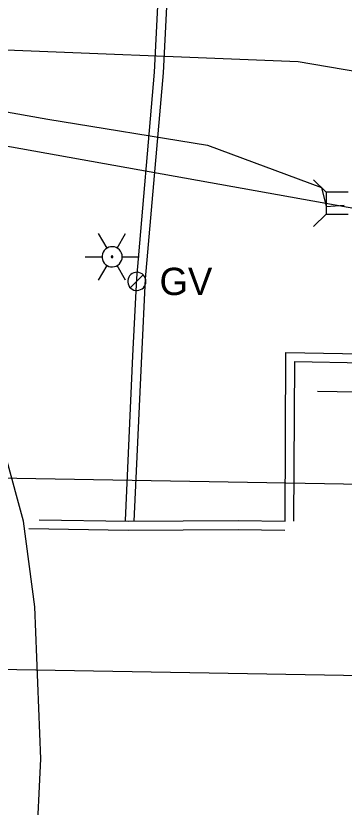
# Model space of a CAD drawing. Extents: x 596028 to 606371, y 330010 to 403088.
# Drawn here: x 604589.6 to 604635.9, y 337984.6 to 338096.2 of the extents above; entities that cross this region are included whole.
import ezdxf

# ---------------------------------------------------------------- set-up
doc = ezdxf.new("R2010")
doc.units = 0
for name, color, linetype in [('E_FTMS_Conduit', 7, 'Continuous'), ('E_LTG', 7, 'Continuous'), ('E_UTL_G', 7, 'Continuous'), ('E_UTL_G_UG', 7, 'Continuous'), ('E_UTL_Overhead', 7, 'Continuous'), ('E_UTL_SAN_UG_MMSD', 7, 'Continuous'), ('E_UTL_T', 7, 'Continuous'), ('E_UTL_T_UG', 7, 'Continuous')]:
    doc.layers.add(name, color=color, linetype=linetype)

# ---------------------------------------------------------------- blocks, each defined once
blk = doc.blocks.new('ACAD_PROXY_ENTITY_15')
at = {"layer": 'E_LTG'}
for points in [[(1843663.8, 1030159.59), (1843660.17, 1030165.87)], [(1843668.16, 1030159.59), (1843671.79, 1030165.87)], [(1843670.34, 1030155.82), (1843670.26, 1030156.64), (1843670.02, 1030157.44), (1843669.64, 1030158.17), (1843669.13, 1030158.82), (1843668.51, 1030159.36), (1843667.79, 1030159.78), (1843667.01, 1030160.05), (1843666.19, 1030160.17), (1843665.36, 1030160.13), (1843664.56, 1030159.93), (1843663.8, 1030159.59), (1843663.13, 1030159.11), (1843662.56, 1030158.51), (1843662.11, 1030157.81), (1843661.8, 1030157.04), (1843661.64, 1030156.23), (1843661.64, 1030155.4), (1843661.8, 1030154.59), (1843662.11, 1030153.82), (1843662.56, 1030153.12), (1843663.13, 1030152.52), (1843663.8, 1030152.04), (1843664.56, 1030151.7), (1843665.36, 1030151.51), (1843666.19, 1030151.47), (1843667.01, 1030151.58), (1843667.79, 1030151.85), (1843668.51, 1030152.27), (1843669.13, 1030152.81), (1843669.64, 1030153.46), (1843670.02, 1030154.2), (1843670.26, 1030154.99), (1843670.34, 1030155.82)], [(1843670.34, 1030155.82), (1843670.26, 1030156.64), (1843670.02, 1030157.44), (1843669.64, 1030158.17), (1843669.13, 1030158.82), (1843668.51, 1030159.36), (1843667.79, 1030159.78), (1843667.01, 1030160.05), (1843666.19, 1030160.17), (1843665.36, 1030160.13), (1843664.56, 1030159.93), (1843663.8, 1030159.59), (1843663.13, 1030159.11), (1843662.56, 1030158.51), (1843662.11, 1030157.81), (1843661.8, 1030157.04), (1843661.64, 1030156.23), (1843661.64, 1030155.4), (1843661.8, 1030154.59), (1843662.11, 1030153.82), (1843662.56, 1030153.12), (1843663.13, 1030152.52), (1843663.8, 1030152.04), (1843664.56, 1030151.7), (1843665.36, 1030151.51), (1843666.19, 1030151.47), (1843667.01, 1030151.58), (1843667.79, 1030151.85), (1843668.51, 1030152.27), (1843669.13, 1030152.81), (1843669.64, 1030153.46), (1843670.02, 1030154.2), (1843670.26, 1030154.99), (1843670.34, 1030155.82)], [(1843670.34, 1030155.82), (1843670.26, 1030156.64), (1843670.02, 1030157.44), (1843669.64, 1030158.17), (1843669.13, 1030158.82), (1843668.51, 1030159.36), (1843667.79, 1030159.78), (1843667.01, 1030160.05), (1843666.19, 1030160.17), (1843665.36, 1030160.13), (1843664.56, 1030159.93), (1843663.8, 1030159.59), (1843663.13, 1030159.11), (1843662.56, 1030158.51), (1843662.11, 1030157.81), (1843661.8, 1030157.04), (1843661.64, 1030156.23), (1843661.64, 1030155.4), (1843661.8, 1030154.59), (1843662.11, 1030153.82), (1843662.56, 1030153.12), (1843663.13, 1030152.52), (1843663.8, 1030152.04), (1843664.56, 1030151.7), (1843665.36, 1030151.51), (1843666.19, 1030151.47), (1843667.01, 1030151.58), (1843667.79, 1030151.85), (1843668.51, 1030152.27), (1843669.13, 1030152.81), (1843669.64, 1030153.46), (1843670.02, 1030154.2), (1843670.26, 1030154.99), (1843670.34, 1030155.82)], [(1843654.37, 1030155.82), (1843661.62, 1030155.82)], [(1843666.34, 1030155.82), (1843666.34, 1030155.88), (1843666.32, 1030155.95), (1843666.29, 1030156.01), (1843666.24, 1030156.07), (1843666.19, 1030156.11), (1843666.13, 1030156.15), (1843666.07, 1030156.17), (1843666, 1030156.18), (1843665.93, 1030156.18), (1843665.86, 1030156.16), (1843665.8, 1030156.13), (1843665.74, 1030156.09), (1843665.69, 1030156.04), (1843665.66, 1030155.98), (1843665.63, 1030155.92), (1843665.62, 1030155.85), (1843665.62, 1030155.78), (1843665.63, 1030155.71), (1843665.66, 1030155.65), (1843665.69, 1030155.59), (1843665.74, 1030155.54), (1843665.8, 1030155.5), (1843665.86, 1030155.47), (1843665.93, 1030155.46), (1843666, 1030155.45), (1843666.07, 1030155.46), (1843666.13, 1030155.49), (1843666.19, 1030155.52), (1843666.24, 1030155.57), (1843666.29, 1030155.62), (1843666.32, 1030155.68), (1843666.34, 1030155.75), (1843666.34, 1030155.82)], [(1843670.34, 1030155.82), (1843677.59, 1030155.82)], [(1843660.17, 1030145.76), (1843663.8, 1030152.04)], [(1843671.79, 1030145.76), (1843668.16, 1030152.04)]]:
    blk.add_lwpolyline(points, dxfattribs=at)

msp = doc.modelspace()

# ---------------------------------------------------------------- linework, layer by layer
at = {"layer": 'E_FTMS_Conduit'}
msp.add_lwpolyline([(604586.79, 337850.4), (604597.83, 337855.35), (604594.44, 337908.62), (604593.95, 337938.1), (604592.48, 337978.69), (604593.09, 337991.4), (604592.23, 338012.83), (604590.67, 338024.91), (604588.22, 338033.89), (604584.13, 338043.61), (604549.18, 338095.05), (604541.85, 338114.6), (604525.21, 338159.57), (604492.18, 338224.83), (604485.27, 338243.18), (604482.26, 338261.55)], dxfattribs=at)
at = {"layer": 'E_UTL_G'}
for points in [[(604607.9, 338058.71), (604607.88, 338058.96), (604607.81, 338059.19), (604607.7, 338059.41), (604607.55, 338059.6), (604607.37, 338059.76), (604607.15, 338059.88), (604606.92, 338059.96), (604606.68, 338060), (604606.44, 338059.98), (604606.2, 338059.93), (604605.98, 338059.83), (604605.78, 338059.68), (604605.61, 338059.51), (604605.48, 338059.3), (604605.39, 338059.08), (604605.34, 338058.84), (604605.34, 338058.59), (604605.39, 338058.35), (604605.48, 338058.13), (604605.61, 338057.92), (604605.78, 338057.74), (604605.98, 338057.6), (604606.2, 338057.5), (604606.44, 338057.44), (604606.68, 338057.43), (604606.92, 338057.47), (604607.15, 338057.55), (604607.37, 338057.67), (604607.55, 338057.83), (604607.7, 338058.02), (604607.81, 338058.24), (604607.88, 338058.47), (604607.9, 338058.71)], [(604605.71, 338057.81), (604607.53, 338059.62)]]:
    msp.add_lwpolyline(points, dxfattribs=at)
at = {"layer": 'E_UTL_G_UG'}
for points in [[(604605.02, 338024.97), (604606.06, 338048.24), (604606.61, 338059.17), (604609.14, 338088.22), (604611.15, 338128.29)], [(604606.27, 338024.92), (604607.31, 338048.18), (604607.86, 338059.09), (604610.39, 338088.14), (604612.4, 338128.23)], [(604592.86, 338025.1), (604605.4, 338024.88), (604620.94, 338024.97), (604627.53, 338024.88), (604627.66, 338048.71), (604659.6, 338048.1), (604660.29, 338024.5), (604661.98, 338024.48), (604678.08, 338023.1), (604703.11, 338023.01), (604728.65, 338022.61), (604754.62, 338022.17), (604788.4, 338021.61), (604836.01, 338021.58), (604864.95, 338021.48), (604896.37, 338021.5), (604900.27, 338026.31), (604935.52, 338026.84), (604967.49, 338026.3), (604985, 338025.85), (604984.37, 338049.04), (604985.32, 338080.05), (604985.44, 338110.91)], [(604628.78, 338024.89), (604628.9, 338047.44), (604658.38, 338046.87), (604659.04, 338024.47)], [(604632.12, 338043.25), (604936.03, 338038.05), (604984.53, 338043.23)], [(604591.38, 338023.88), (604605.39, 338023.63), (604620.94, 338023.72), (604627.51, 338023.65)]]:
    msp.add_lwpolyline(points, dxfattribs=at)
at = {"layer": 'E_UTL_Overhead'}
msp.add_lwpolyline([(604103.64, 338065.21), (604129.71, 338064.26), (604269.62, 338062.62), (604344.53, 338119.28), (604560.83, 338082.73), (604641.4, 338068.29), (604696.28, 338059.45), (604715.56, 338054.88), (604786.57, 338054.03), (604829.08, 338053.72), (604872.92, 338052.19), (604977.47, 338050.01), (605123.72, 338048.42), (605215.39, 338038.9)], dxfattribs=at)
at = {"layer": 'E_UTL_SAN_UG_MMSD'}
for p, q in [((604202.07, 338037.6), (604640.48, 338030.1)), ((603897.65, 338015.8), (604665.17, 338002.68))]:
    msp.add_line(p, q, dxfattribs=at)
at = {"layer": 'E_UTL_T'}
for points in [[(604633.31, 338071.3), (604631.56, 338073.05)], [(604636.41, 338071.3), (604633.31, 338071.3)], [(604633.31, 338071.3), (604633.31, 338068.2)], [(604633.31, 338068.2), (604631.56, 338066.45)], [(604633.31, 338068.2), (604636.41, 338068.2)]]:
    msp.add_lwpolyline(points, dxfattribs=at)
at = {"layer": 'E_UTL_T_UG'}
for points in [[(604565.56, 338094.25), (604582.26, 338091.62), (604629.37, 338089.71), (604674.9, 338081.98)], [(604562.54, 338087.2), (604594.09, 338081.58), (604616.58, 338077.92), (604632.65, 338071.98), (604633.31, 338069.27), (604635.85, 338069.47)]]:
    msp.add_lwpolyline(points, dxfattribs=at)

# ---------------------------------------------------------------- block references
at = {"layer": 'E_LTG', "xscale": 0.32808333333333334, "yscale": 0.32808333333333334}
msp.add_blockref('ACAD_PROXY_ENTITY_15', (-272.94, 85.23), dxfattribs=at)

# ---------------------------------------------------------------- texts
at = {"layer": 'E_UTL_G'}
msp.add_text('GV', height=3.85, dxfattribs=at).set_placement((604609.83, 338056.79))

doc.saveas('drawing.dxf')
